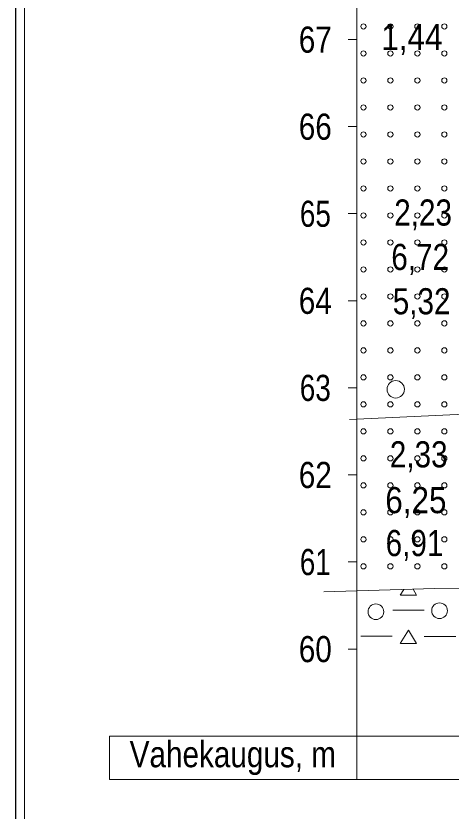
# Model space of a CAD drawing. Extents: x 640121 to 640955, y 6441885 to 6442246.
# Drawn here: x 640121.3 to 640171.3, y 6442059.4 to 6442150.7 of the extents above; entities that cross this region are included whole.
import ezdxf
from ezdxf.enums import TextEntityAlignment as Align

# ---------------------------------------------------------------- set-up
doc = ezdxf.new("R2010")
doc.units = 0
doc.header["$LTSCALE"] = 1.2
for name, color, linetype, lineweight in [('30', 7, 'Continuous', 13), ('31', 7, 'Continuous', 13), ('32', 7, 'Continuous', 13), ('33', 7, 'Continuous', 13), ('34', 7, 'Continuous', 25), ('43', 7, 'Continuous', 13), ('46', 7, 'Continuous', 13), ('47', 7, 'Continuous', 13), ('50', 7, 'Continuous', 13)]:
    doc.layers.add(name, color=color, linetype=linetype, lineweight=lineweight)

msp = doc.modelspace()

# ---------------------------------------------------------------- linework, layer by layer
at = {"layer": '30'}
for p, q in [((640160.5, 6442063), (640160.5, 6442218)), ((640159.5, 6442148), (640160.5, 6442148)), ((640159.5, 6442138), (640160.5, 6442138)), ((640159.5, 6442128), (640160.5, 6442128)), ((640159.5, 6442118), (640160.5, 6442118)), ((640159.5, 6442108), (640160.5, 6442108)), ((640159.5, 6442098), (640160.5, 6442098)), ((640159.5, 6442088), (640160.5, 6442088)), ((640159.5, 6442078), (640160.5, 6442078)), ((640132.09, 6442068), (640510.5, 6442068)), ((640132.09, 6442063), (640132.09, 6442068)), ((640132.09, 6442063), (640510.5, 6442063))]:
    msp.add_line(p, q, dxfattribs=at)
at = {"layer": '31'}
msp.add_lwpolyline([(640156.71, 6442084.57), (640169.39, 6442084.94), (640174.39, 6442085), (640185.27, 6442085.01), (640198.57, 6442085.15), (640211.29, 6442085.53), (640222.23, 6442086.04), (640236.05, 6442086.58), (640247.59, 6442087.26), (640261.87, 6442089), (640272.13, 6442093.03), (640281.27, 6442096.49), (640290.79, 6442099.48), (640306.37, 6442104.48), (640328.11, 6442110.01), (640342.33, 6442112.86), (640361.6, 6442115.89), (640378.77, 6442118.83), (640434.25, 6442118.61), (640476.5, 6442139.76), (640496.42, 6442148.93), (640502.36, 6442149.59), (640510.5, 6442150.13)], dxfattribs=at)
at = {"layer": '34', "lineweight": 13}
msp.add_lwpolyline([(640159.63, 6442104.37), (640185.19, 6442105.55), (640261.87, 6442109), (640328.12, 6442114), (640360.69, 6442114.7)], dxfattribs=at)
at = {"layer": '43'}
for centre in [(640161.244, 6442149.496), (640164.344, 6442149.496), (640167.444, 6442149.496), (640170.544, 6442149.496), (640161.244, 6442146.396), (640164.344, 6442146.396), (640167.444, 6442146.396), (640170.544, 6442146.396), (640161.244, 6442143.296), (640164.344, 6442143.296), (640167.444, 6442143.296), (640170.544, 6442143.296), (640161.244, 6442140.196), (640164.344, 6442140.196), (640167.444, 6442140.196), (640170.544, 6442140.196), (640161.244, 6442137.096), (640164.344, 6442137.096), (640167.444, 6442137.096), (640170.544, 6442137.096), (640161.244, 6442133.996), (640164.344, 6442133.996), (640167.444, 6442133.996), (640170.544, 6442133.996), (640161.244, 6442130.896), (640164.344, 6442130.896), (640167.444, 6442130.896), (640170.544, 6442130.896), (640161.244, 6442127.796), (640164.344, 6442127.796), (640167.444, 6442127.796), (640170.544, 6442127.796), (640161.244, 6442124.696), (640164.344, 6442124.696), (640167.444, 6442124.696), (640170.544, 6442124.696), (640161.244, 6442121.596), (640164.344, 6442121.596), (640167.444, 6442121.596), (640170.544, 6442121.596), (640161.244, 6442118.496), (640164.344, 6442118.496), (640167.444, 6442118.496), (640170.544, 6442118.496), (640161.244, 6442115.396), (640164.344, 6442115.396), (640167.444, 6442115.396), (640170.544, 6442115.396), (640161.244, 6442112.296), (640164.344, 6442112.296), (640167.444, 6442112.296), (640170.544, 6442112.296), (640161.244, 6442109.196), (640164.344, 6442109.196), (640167.444, 6442109.196), (640170.544, 6442109.196), (640161.244, 6442106.096), (640164.344, 6442106.096), (640167.444, 6442106.096), (640170.544, 6442106.096), (640161.244, 6442102.996), (640164.344, 6442102.996), (640167.444, 6442102.996), (640170.544, 6442102.996), (640161.244, 6442099.896), (640164.344, 6442099.896), (640167.444, 6442099.896), (640170.544, 6442099.896), (640161.244, 6442096.796), (640164.344, 6442096.796), (640167.444, 6442096.796), (640170.544, 6442096.796), (640161.244, 6442093.696), (640164.344, 6442093.696), (640167.444, 6442093.696), (640170.544, 6442093.696), (640161.244, 6442090.596), (640164.344, 6442090.596), (640167.444, 6442090.596), (640170.544, 6442090.596), (640161.244, 6442087.496), (640164.344, 6442087.496), (640167.444, 6442087.496), (640170.544, 6442087.496)]:
    msp.add_circle(centre, 0.3, dxfattribs=at)
at = {"layer": '46'}
for p, q in [((640168.24, 6442082.45), (640164.64, 6442082.45)), ((640164.54, 6442079.46), (640160.94, 6442079.46)), ((640171.84, 6442079.45), (640168.24, 6442079.45))]:
    msp.add_line(p, q, dxfattribs=at)
for points in [[(640165.48, 6442084.18), (640165.48, 6442084.2), (640165.87, 6442084.84)], [(640166.95, 6442084.87), (640167.36, 6442084.19), (640165.56, 6442084.2)], [(640165.48, 6442078.62), (640165.48, 6442078.65), (640166.43, 6442080.18), (640167.36, 6442078.64), (640165.56, 6442078.65)]]:
    msp.add_lwpolyline(points, dxfattribs=at)
for centre in [(640162.674, 6442082.279), (640169.987, 6442082.401)]:
    msp.add_circle(centre, 0.9, dxfattribs=at)
at = {"layer": '47'}
msp.add_circle((640164.954, 6442107.827), 1, dxfattribs=at)
at = {"layer": '50', "lineweight": 25}
msp.add_lwpolyline([(640121.33, 6442246.16), (640955.23, 6442246.16), (640955.23, 6441889.4), (640121.33, 6441889.4)], close=True, dxfattribs=at)
at = {"layer": '50'}
msp.add_lwpolyline([(640122.33, 6442245.16), (640954.23, 6442245.16), (640954.23, 6441890.4), (640122.33, 6441890.4)], close=True, dxfattribs=at)

# ---------------------------------------------------------------- texts
at = {"layer": '30'}
for s, width, p in [('67', 0.85, (640155.715, 6442146.49)), ('66', 0.85, (640155.715, 6442136.49)), ('65', 0.8, (640155.725, 6442126.49)), ('64', 0.85, (640155.715, 6442116.49)), ('63', 0.8, (640155.715, 6442106.49)), ('62', 0.85, (640155.715, 6442096.49)), ('61', 0.8, (640155.72, 6442086.49)), ('60', 0.85, (640155.715, 6442076.49)), ('Vahekaugus, m', 0.85, (640146.245, 6442064.42))]:
    msp.add_text(s, height=3, dxfattribs=dict(at, width=width)).set_placement(p, align=Align.CENTER)
at = {"layer": '32'}
for s, width, p in [('1,44', 0.9, (640166.815, 6442146.78)), ('2,23', 0.85, (640168.1, 6442126.63)), ('5,32', 0.85, (640167.93, 6442116.44)), ('2,33', 0.85, (640167.595, 6442098.86)), ('6,91', 0.85, (640167.115, 6442088.67))]:
    msp.add_text(s, height=3, dxfattribs=dict(at, width=width)).set_placement(p, align=Align.CENTER)
at = {"layer": '33'}
for s, width, p in [('6,72', 0.85, (640167.765, 6442121.53)), ('6,25', 0.9, (640167.27, 6442093.6))]:
    msp.add_text(s, height=3, dxfattribs=dict(at, width=width)).set_placement(p, align=Align.CENTER)

doc.saveas('drawing.dxf')
